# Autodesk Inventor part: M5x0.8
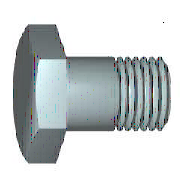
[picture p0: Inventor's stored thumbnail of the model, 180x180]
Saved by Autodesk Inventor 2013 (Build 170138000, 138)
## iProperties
IsCustomPart: 1
Created: 2009-02
Part Number: M5x0.8
Material: 강, 연강
Description: 6각 머리 볼트 및 6각 머리 나사
Document SubType Name: Modeling
Standard: KS B 1002
Designer: 한국산업디자인학원
Standards Organization: KS
Language: ko-KR
Size Designation: A  M 5 x 25
Categories: <MemberInstance><Categories><Category DisplayName="조임쇠" InternalName="e4da775c-781d-43d5-af7c-5136215cf5a6" Mnemonic="FSTN"><Category DisplayName="볼트" InternalN
Density: 1 g/cm^3
Author: 한국산업디자인학원
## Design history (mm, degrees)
sketch "스케치1"
  geometry: L1 (0, 2.5)-(0, 2.5); L2 (1, 2.5)-(12, 2.5); L3 (12, 2.5)-(12, 0); L4 (12, 0)-(-0.5, 0); L5 (-3, 0)-(14.5, 0) reference; L6 (-0.5, 0)-(-0.5, 2.5); L7 (-0.5, 2.5)-(0, 2.5); L8 (1, 2.5)-(0.509, 2.5); L9 (0.509, 2.5)-(0, 2.5); L10 (0, -0.5)-(0, 3) reference
  constraints: 16 end point, 3 collinear, 2 perpendicular
  dimensions: "d0" = 12 distance between parallel lines of L3 L1; "d1" = 11 distance from line of L2.start L3; "d2" = 5 diameter of L2 L4 (= GD); "d9" = 0.5001 distance between parallel lines of L6 L1 (computed from SD); "d10" = 5 diameter of L7 L4 (= d2); "d13" = 0.49086 distance of L2.start L8.end (computed from GAL); "d14" = 5 diameter of L9 L4 (= BDM)
revolve "본체" sketch "스케치1" stored, may be unused: angle "d12" = 90 deg
sketch "스케치2"
  geometry: L1 (0, 4.619)-(4, 2.309); L2 (4, 2.309)-(4, -2.309); L3 (4, -2.309)-(0, -4.619); L4 (0, -4.619)-(-4, -2.309); L5 (-4, -2.309)-(-4, 2.309); L6 (-4, 2.309)-(0, 4.619); 2 further points
  constraints: 12 end point, 1 coincident, 1 vertical, 11 other
  dimensions: "d11" = 8 distance between parallel lines of L5 L2 (= SW)
extrude "머리" join sketch "스케치2" distance "d3" = 3 (= KOH - SD); taper "d4" = 0 deg
sketch "스케치4"
  geometry: L1 (-3.5, 4)-(-3.5, 4.619); L2 (-3.5, 4.619)-(-3.143, 4.619); L3 (-3.143, 4.619)-(-3.5, 4); L4 (-4.1, 0)-(0.1, 0) reference; L5 (-0.5, 4.619)-(-3.5, 4.619) reference; L6 (-3.5, 2.309)-(-3.5, 4.619) reference
  constraints: 6 end point, 2 collinear, 1 perpendicular, 1 vertical
  dimensions: "d5" = 30 deg angle of L3 L1 (= ANG1); "d19" = 8 diameter of L1.start L4 (= SW0)
revolve "모따기1" sketch "스케치4" stored, may be unused: angle "d21" = 90 deg
workplane "Work Plane1"
body "Solid1"
feature "스레드" dims "d15" = 12, "d16" = 0
chamfer "모따기2" distance "d6" = 0.49076 (= -0.5 x SPD + 0.5 x GD); stored, may be unused: second distance "d7" = 0.49086 (computed from GUL), angle "d55" = 45 deg
other parameters: "NLG" = 25 [user parameter], "GD" = 5 (= NND) [user parameter; used in 2 equation terms], "BDM" = 5 (= NND) [user parameter; used in 1 equation term], "KOH" = 3.5 [user parameter; used in 1 equation term], "GEL" = 16 [user parameter], "SW" = 8 [user parameter; used in 3 equation terms], "SW0" = 8 (= SW) [user parameter; used in 1 equation term], "SPD" = 4.01848 (= NND - 1.2269 x PTC) [user parameter; used in 1 equation term], "SD2" = 6.88 (= SDH) [user parameter], "SD" = 0.5 [user parameter; used in 2 equation terms], "ANG1" = 30 deg [user parameter; used in 1 equation term], "GAL" = 0.49076 (= 0.61345 x PTC) [user parameter; used in 1 equation term], "GUL" = 0.49076 (= 0.61345 x PTC) [user parameter; used in 1 equation term], "d8" = 0, "RR" = 0.2 [user parameter], "d57" = 0, "d58" = 0, "TPU" = 12.5 (computed from PTC) [user parameter], "GD1" = 4.01848 (= THREADDIA - 1.2269 x PTC) [user parameter], "THREADDIA" = 5 [user parameter; used in 1 equation term], "SDH" = 6.88 [user parameter; used in 1 equation term], "TOA" = 30 deg [user parameter], "PTC" = 0.8 [user parameter; used in 5 equation terms], "NND" = 5 [user parameter; used in 3 equation terms], "E0" = 9.24 (= 1.155 x SW) [user parameter]
